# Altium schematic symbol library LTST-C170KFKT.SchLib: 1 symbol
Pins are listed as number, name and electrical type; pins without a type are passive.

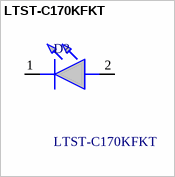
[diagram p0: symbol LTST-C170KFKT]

## LTST-C170KFKT
designator D?
Standard LEDs - SMD Orange Clear 605nm; Manufacturer_Name: Lite-On; Geometry.Height: 1.2mm
footprint LEDC2012X120N
pins: 1 K, 2 A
